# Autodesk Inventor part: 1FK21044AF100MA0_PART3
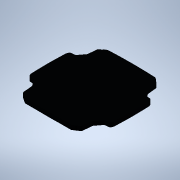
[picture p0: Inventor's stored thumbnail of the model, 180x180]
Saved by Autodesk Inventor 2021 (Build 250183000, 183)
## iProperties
Created: 2025-04
Part Number: 1FK21044AF100MA0_PART3
Material: Generic
Catalog Web Link: www.3dfindit.com
Description: -Servo synchronous motor
Document SubType Name: Modeling
Designer: psAdmin
Mass: 21.7019 g
Surface Area: 120.085 cm^2
Volume: 21.7019 cm^3
Density: 1 g/cm^3
Appearance: PSOLRGB-38-46-56
Category: PARTsolutions
Title: 1FK21044AF100MA0_PART3
Author: Cadenas PARTsolutions
Comments: Servo synchronous motor
Sending System: PARTsolutions
Preprocessor: ST-DEVELOPER v19.3
PSOL_IDENT_0: {$CADENAS_DATA/23d-libs/siemens_ag/_cat_/ec/e4/1fk21044af100ma0.prj},213 {VTYP=3D},{NB=1FK21044AF100
PSOL_IDENT_1: MA0_PART3},{LINA=1FK21044AF100MA0_PART3},{NN=1FK21044AF100MA0_PART3},{NOPRJ=TRUE},{DATE=19.08.2025 1
PSOL_IDENT_2: 4:01:05},{GEOMDATE=30.07.2025 02:01:01},{VERSION=},{LINEID=10},{WBVAR=},{WBNUMERIC=}  {NB=1FK21044AF
PSOL_IDENT_3: 100MA0_PART3},{LINA=1FK21044AF100MA0_PART3},{KT=DUMMY},{PREVIEW=../../../_pool_/cb/72/p_d211_xx_0043
PSOL_IDENT_4: 4j.png},{DESCSHORT=SIMOTICS S-1FK2 HD, SINAMICS S210 3AC 400V-480V, 1.27 Nm, 3000 rpm},{DESCLONG=SIM
PSOL_IDENT_5: OTICS S-1FK2 HD servo motor M0=1.27 Nm; PN = 0.4 kW at nN=3000 rpm (380-480 V); PN = 0.2 kW at nN=15
PSOL_IDENT_6: 00 rpm (200-240 V); with holding brake; degree of protection IP64; cylindrical shaft D19x40mm; absol
PSOL_IDENT_7: ute encoder 22-bit + 12-bit multiturn (encoder AM22DQC); with OCC interface; plug size M17, rotatabl
PSOL_IDENT_8: e; SIMOTICS S-1FK2 servomotorfor a wide range of uses in industrial environments. SIMOTICS S‑1FK2 se
PSOL_IDENT_9: rvomotors are compact synchronous motors with a high dynamic performance that set themselves apart a
PSOL_IDENT_10: s a result of their high power density, degree of protection and overload capability. The motors are
PSOL_IDENT_11: available in two variants: as High Dynamic variant (highest dynamic performance as a result of the
PSOL_IDENT_12: low intrinsic moment of inertia for applications demanding a high dynamic performance with low moved
PSOL_IDENT_13: masses) - and as Compact variant (precise and stable closed-loop control for medium up to large mov
PSOL_IDENT_14: ed masses as a result of a medium intrinsic moment of inertia). SIMOTICSS‑1FK2 servomotors fully exp
PSOL_IDENT_15: loit their strengths in a system with the SINAMICSS210 frequency converter and simple connection usi
PSOL_IDENT_16: ng the one cable connection (OCC). Advantages include the short control and positioning times, fast
PSOL_IDENT_17: and precise correction of disturbing quantities as well as stable control with a high dynamic perfor
PSOL_IDENT_18: mance. The servo motors can be configured to address a wide range of requirements. For example with
PSOL_IDENT_19: and without holding brake, IP64 or IP65 degree of protection, singleturn or multiturn absolute encod
PSOL_IDENT_20: ers - to name just a few. Further, the servomotors are available in different shaft heights extendin
PSOL_IDENT_21: g from 20 to 100. A shaft sealing ring is available to achieve an IP65 degree of protection and for
PSOL_IDENT_22: subsequent mounting at the motor or as spare part. SIMOTICS - the optimum motor for each and every m
PSOL_IDENT_23: otion control application.},{INTNO=195125043275},{SUPPLIERALTNO=1FK2104-4AF10-0MA0},{MANUID=1FK21044
PSOL_IDENT_24: AF100MA0},{MANUNAME=Siemens},{MANUTYPEDESC=Synchronous motor 1FK2-HD 1.27 NM},{AAU732=SIMOTICS},{AAO
PSOL_IDENT_25: 057=S-1FK2},{AAU734=SIMOTICS S-1FK2 HD servo motor M0=1.27 Nm; PN = 0.4 kW at nN=3000 rpm (380-480 V
PSOL_IDENT_26: ); PN = 0.2 kW at nN=1500 rpm (200-240 V); with holding brake; degree of protection IP64; cylindrica
PSOL_IDENT_27: l shaft D19x40mm; absolute encoder 22-bit + 12-bit multiturn (encoder AM22DQC); with OCC interface;
PSOL_IDENT_28: plug size M17, rotatable;},{AAW338=Synchronous motor 1FK2-HD 1.27 NM},{AAO742=SIMOTICS},{AAO663=4042
PSOL_IDENT_29: 948694015},{NOCUPEROU=1},{PRICEQUANTITY=1},{QUANTITYMIN=1},{QUANTITYINT=1},{CTN=85015100},{COO=DE},{
PSOL_IDENT_30: AAO676=1FK2104-4AF10-0MA0},{AAO677=Siemens AG},{ORDERUNIT=C62},{CONTENTUNIT=C62}
NB: 1FK21044AF100MA0_PART3
NT: Servo synchronous motor
NBSYN: $MANUID._PART3
LINA: 1FK21044AF100MA0_PART3
CATALOG: SIEMENS
PREVIEW: ../../../_pool_/cb/72/p_d211_xx_00434j.png
DESCSHORT: SIMOTICS S-1FK2 HD, SINAMICS S210 3AC 400V-480V, 1.27 Nm, 3000 rpm
DESCLONG: SIMOTICS S-1FK2 HD servo motor M0=1.27 Nm; PN = 0.4 kW at nN=3000 rpm (380-480 V); PN = 0.2 kW at nN=1500 rpm (200-240 V); with holding brake; degree of protect
INTNO: 195125043275
SUPPLIERALTNO: 1FK2104-4AF10-0MA0
MANUID: 1FK21044AF100MA0
MANUNAME: Siemens
MANUTYPEDESC: Synchronous motor 1FK2-HD 1.27 NM
AAU732: SIMOTICS
AAO057: S-1FK2
AAU734: SIMOTICS S-1FK2 HD servo motor M0=1.27 Nm; PN = 0.4 kW at nN=3000 rpm (380-480 V); PN = 0.2 kW at nN=1500 rpm (200-240 V); with holding brake; degree of protect
AAW338: Synchronous motor 1FK2-HD 1.27 NM
AAO742: SIMOTICS
AAO663: 4042948694015.0
NOCUPEROU: 1
PRICEQUANTITY: 1
QUANTITYMIN: 1
QUANTITYINT: 1
CTN: 85015100
COO: DE
ARTICLENO: 1FK21044AF100MA0_PART3
BOMINFO: 1FK21044AF100MA0_PART3
CREATOR: CADENAS GmbH
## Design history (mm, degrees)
feature "2025_04_17_15_33_01_0580"
body "Solid1"
